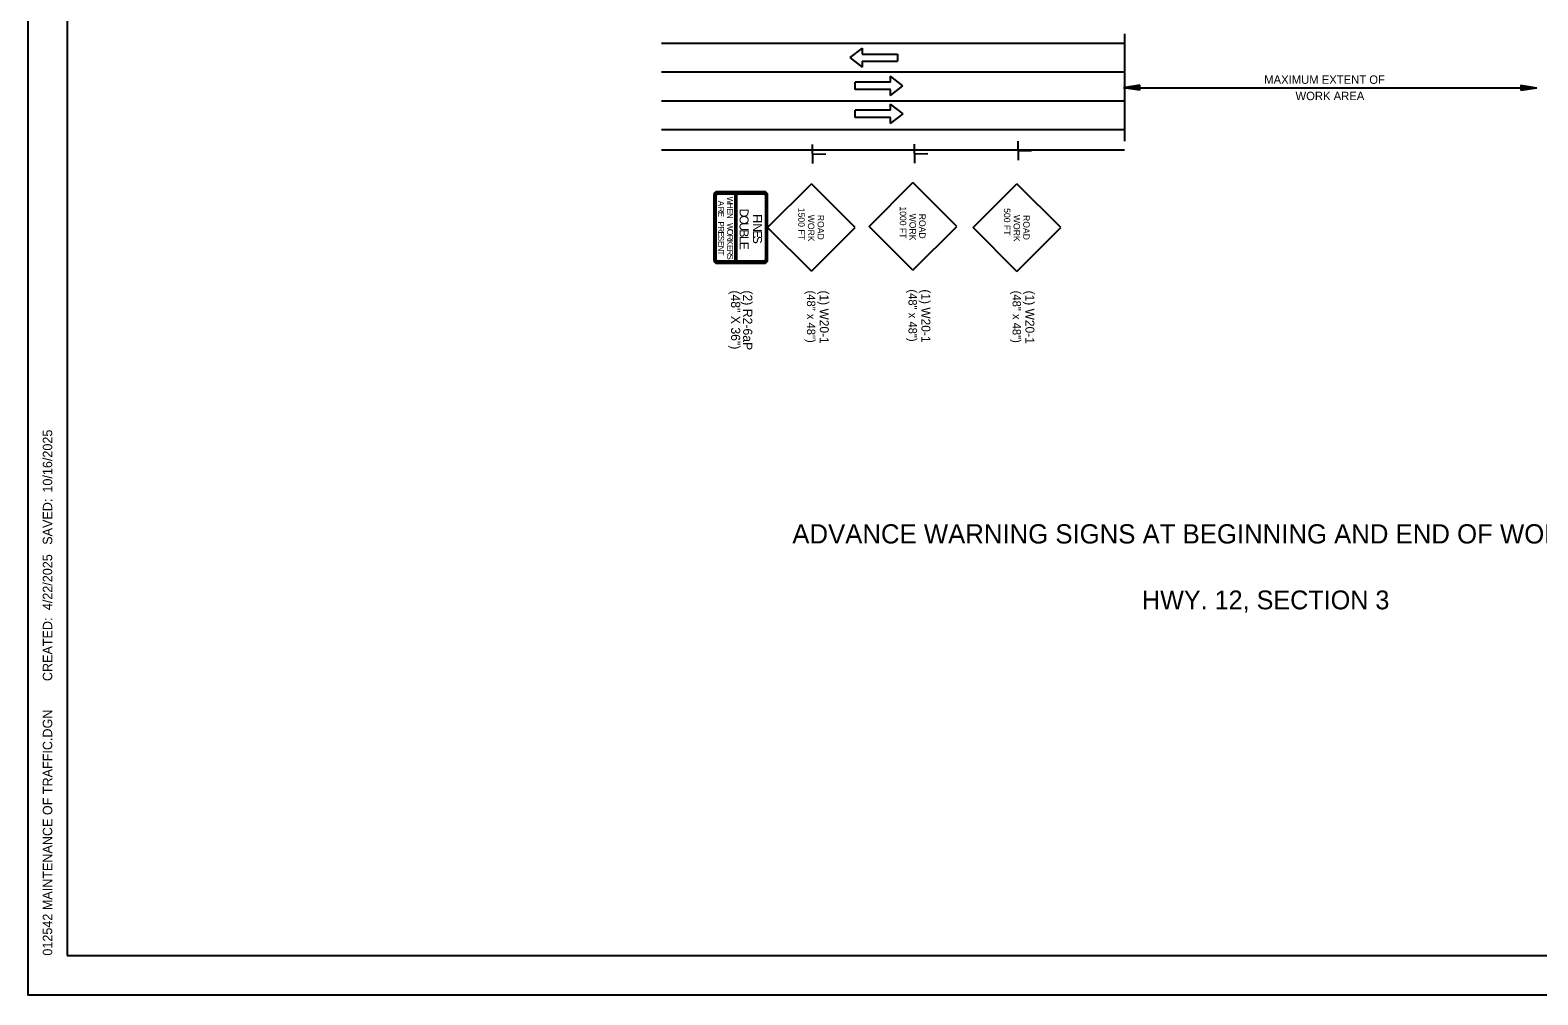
# Model space of a CAD drawing. Extents: x 32485 to 39285, y 55121 to 58033.
# Drawn here: x 35886 to 36848, y 56764 to 57379 of the extents above; entities that cross this region are included whole.
import ezdxf

# ---------------------------------------------------------------- set-up
doc = ezdxf.new("R2010")
doc.units = 0
for name, color, linetype in [('Default', 7, 'Continuous'), ('R_Border', 7, 'Continuous'), ('R_Border Notes', 7, 'Continuous'), ('R_Draft', 7, 'Continuous'), ('R_Exist Surface', 7, 'Continuous'), ('SHET_Annotations', 7, 'Continuous')]:
    doc.layers.add(name, color=color, linetype=linetype)

msp = doc.modelspace()

# ---------------------------------------------------------------- linework, layer by layer
at = {"layer": 'Default'}
for p, q in [((36584.44, 57376.82), (36584.44, 57308.4)), ((36417.17, 57367.79), (36409.21, 57361.65)), ((36417.17, 57367.79), (36417.17, 57363.95)), ((36409.21, 57361.65), (36417.17, 57355.51)), ((36417.17, 57363.95), (36439.74, 57363.95)), ((36417.17, 57359.35), (36439.74, 57359.35)), ((36417.17, 57359.35), (36417.17, 57355.51)), ((36439.74, 57363.95), (36439.74, 57359.35)), ((36435.16, 57345.92), (36435.16, 57349.76)), ((36443.13, 57343.62), (36435.16, 57349.76)), ((36435.16, 57345.92), (36412.59, 57345.92)), ((36412.59, 57341.32), (36412.59, 57345.92)), ((36435.16, 57341.32), (36412.59, 57341.32)), ((36435.16, 57337.48), (36443.13, 57343.62)), ((36435.16, 57337.48), (36435.16, 57341.32)), ((36583.93, 57342.47), (36847.55, 57342.47)), ((36641.23, 57342.47), (36790.25, 57342.47)), ((36435.27, 57328.12), (36412.7, 57328.12)), ((36412.7, 57323.52), (36412.7, 57328.12)), ((36435.27, 57328.12), (36435.27, 57331.96)), ((36443.24, 57325.82), (36435.27, 57331.96)), ((36435.27, 57323.52), (36412.7, 57323.52)), ((36435.27, 57319.68), (36443.24, 57325.82)), ((36435.27, 57319.68), (36435.27, 57323.52)), ((36322.59, 57274.02), (36322.59, 57232.62)), ((36323.18, 57274.02), (36323.18, 57232.62)), ((36324.02, 57232.62), (36324.02, 57274.02)), ((36354.71, 57276.16), (36324.73, 57276.16)), ((36354.71, 57275.56), (36324.73, 57275.56)), ((36324.73, 57274.73), (36354.71, 57274.73)), ((36336.21, 57231.9), (36336.21, 57274.73)), ((36336.21, 57274.73), (36337.04, 57274.73)), ((36337.04, 57274.73), (36337.04, 57231.9)), ((36355.43, 57274.02), (36355.43, 57232.62)), ((36356.26, 57232.62), (36356.26, 57274.02)), ((36356.85, 57232.62), (36356.85, 57274.02)), ((36354.71, 57231.9), (36324.73, 57231.9)), ((36337.04, 57231.9), (36336.21, 57231.9)), ((36324.73, 57231.07), (36354.71, 57231.07)), ((36324.73, 57230.47), (36354.71, 57230.47))]:
    msp.add_line(p, q, dxfattribs=at)
msp.add_lwpolyline([(35885, 57863.91), (35885, 56763.91), (37585, 56763.91), (37585, 57863.91)], close=True, dxfattribs=at)
for centre, radius, start, end in [((36324.73, 57274.02), 2.14, 90, 180.00001), ((36324.73, 57274.02), 1.55, 90.00001, 180), ((36324.73, 57274.02), 0.714, 90.00001, 180), ((36354.71, 57274.02), 2.14, 0, 90), ((36354.71, 57274.02), 1.55, 0, 90.00001), ((36354.71, 57274.02), 0.714, 0, 90.00001), ((36324.73, 57232.62), 2.14, 180.00001, 270.00001), ((36324.73, 57232.62), 1.55, 180, 270.00001), ((36324.73, 57232.62), 0.714, 180, 270.00001), ((36354.71, 57232.62), 2.14, 270, 0), ((36354.71, 57232.62), 1.55, 270, 0), ((36354.71, 57232.62), 0.714, 270, 0)]:
    msp.add_arc(centre, radius, start, end, dxfattribs=at)
at = {"layer": 'R_Border'}
for p, q in [((36385.59, 57294.1), (36385.38, 57306.15)), ((36385.66, 57300.1), (36393.89, 57300.24)), ((36450.68, 57294.4), (36450.48, 57306.45)), ((36450.75, 57300.4), (36458.98, 57300.54)), ((36516.84, 57296.31), (36516.64, 57308.36)), ((36516.92, 57302.31), (36525.14, 57302.45)), ((36356.85, 57253.32), (36384.73, 57281.22)), ((36412.63, 57253.32), (36384.73, 57281.22)), ((36421.65, 57254.03), (36449.53, 57281.93)), ((36477.43, 57254.03), (36449.53, 57281.93)), ((36488.02, 57253.22), (36515.9, 57281.13)), ((36543.8, 57253.22), (36515.9, 57281.13)), ((36384.73, 57225.42), (36356.85, 57253.32)), ((36384.73, 57225.42), (36412.63, 57253.32)), ((36449.53, 57226.13), (36421.65, 57254.03)), ((36449.53, 57226.13), (36477.43, 57254.03)), ((36515.9, 57225.32), (36488.02, 57253.22)), ((36515.9, 57225.32), (36543.8, 57253.22))]:
    msp.add_line(p, q, dxfattribs=at)
at = {"layer": 'R_Border Notes'}
for points in [[(35885, 56763.91), (37585, 56763.91), (37585, 57863.91), (35885, 57863.91)], [(35910, 56788.91), (37560, 56788.91), (37560, 57838.91), (35910, 57838.91)]]:
    msp.add_lwpolyline(points, close=True, dxfattribs=at)
at = {"layer": 'R_Draft'}
for p, q in [((36594.16, 57344.01), (36583.93, 57342.47)), ((36594.16, 57340.94), (36583.93, 57342.47)), ((36594.16, 57343.75), (36585.64, 57342.47)), ((36594.16, 57341.19), (36585.64, 57342.47)), ((36594.16, 57343.49), (36587.4, 57342.47)), ((36594.16, 57341.46), (36587.4, 57342.47)), ((36594.16, 57343.24), (36589.1, 57342.47)), ((36594.16, 57341.71), (36589.1, 57342.47)), ((36594.16, 57342.97), (36590.84, 57342.47)), ((36594.16, 57341.98), (36590.84, 57342.47)), ((36594.16, 57342.71), (36592.55, 57342.47)), ((36594.16, 57342.23), (36592.55, 57342.47)), ((36594.16, 57340.94), (36594.16, 57344.01)), ((36837.32, 57344.01), (36847.55, 57342.47)), ((36837.32, 57344.01), (36837.32, 57340.94)), ((36837.32, 57343.75), (36845.84, 57342.47)), ((36837.32, 57343.49), (36844.08, 57342.47)), ((36837.32, 57343.24), (36842.38, 57342.47)), ((36837.32, 57342.97), (36840.64, 57342.47)), ((36837.32, 57342.71), (36838.94, 57342.47)), ((36837.32, 57340.94), (36847.55, 57342.47)), ((36837.32, 57341.97), (36840.64, 57342.47)), ((36837.32, 57341.46), (36844.08, 57342.47)), ((36837.32, 57341.19), (36845.84, 57342.47)), ((36837.32, 57341.71), (36842.38, 57342.47)), ((36837.32, 57342.23), (36838.94, 57342.47))]:
    msp.add_line(p, q, dxfattribs=at)
at = {"layer": 'R_Exist Surface'}
for p, q in [((36289.08, 57370.98), (36584.44, 57370.98)), ((36289.08, 57352.58), (36584.44, 57352.58)), ((36289.08, 57334.17), (36584.44, 57334.17)), ((36289.08, 57315.76), (36584.44, 57315.76)), ((36289.05, 57302.95), (36584.42, 57302.95))]:
    msp.add_line(p, q, dxfattribs=at)

# ---------------------------------------------------------------- texts
at = {"layer": 'Default'}
for s, height, p in [('MAXIMUM EXTENT OF ', 5.3695, (36673.61, 57344.96)), ('WORK AREA', 5.37, (36693.57, 57334.54)), ('ADVANCE WARNING SIGNS AT BEGINNING AND END OF WORK ZONE ', 12.2732, (36372.6, 57051.78)), ('HWY. 12, SECTION 3', 12, (36595.63, 57009.79))]:
    msp.add_text(s, height=height, dxfattribs=at).set_placement(p)
for s, height, p in [('A', 3.81, (36325.27, 57270.37)), ('W', 3.81, (36330.98, 57273.02)), ('R', 3.81, (36325.27, 57266.56)), ('E', 3.81, (36325.27, 57263.33)), ('H', 3.81, (36330.98, 57269.06)), ('E', 3.81, (36330.98, 57265.56)), ('N', 3.81, (36330.98, 57262.55)), ('O', 5.71, (36338.95, 57261.08)), ('D', 5.71, (36338.95, 57265.31)), ('F', 5.71, (36347.51, 57261.83)), ('P', 3.81, (36325.27, 57257.16)), ('R', 3.81, (36325.27, 57254)), ('O', 3.81, (36330.98, 57252.27)), ('W', 3.81, (36330.98, 57256.15)), ('U', 5.71, (36338.95, 57256.57)), ('B', 5.71, (36338.95, 57252.12)), ('I', 5.71, (36347.51, 57258.11)), ('N', 5.71, (36347.51, 57256.06)), ('E', 5.71, (36347.51, 57251.6)), ('S', 3.81, (36325.27, 57248.02)), ('E', 3.81, (36325.27, 57250.77)), ('E', 3.81, (36325.27, 57244.79)), ('N', 3.81, (36325.27, 57241.78)), ('R', 3.81, (36330.98, 57248.73)), ('K', 3.81, (36330.98, 57245.49)), ('E', 3.81, (36330.98, 57242.18)), ('L', 5.71, (36338.95, 57247.95)), ('E', 5.71, (36338.95, 57244.24)), ('S', 5.71, (36347.51, 57248.01)), ('T', 3.81, (36325.27, 57238.62)), ('S', 3.81, (36330.98, 57236.2)), ('R', 3.81, (36330.98, 57239.17))]:
    msp.add_text(s, height=height, rotation=270, dxfattribs=at).set_placement(p)
at = {"layer": 'R_Border'}
for s, height, rotation, p in [('1500 FT', 4.11, 270.00057, (36376.37, 57265.89)), ('WORK', 4.11, 270.00004, (36382.54, 57261.46)), ('ROAD', 4.11, 270.00045, (36388.71, 57261.38)), ('1000 FT', 4.11, 270.00057, (36441.17, 57266.77)), ('WORK', 4.11, 270.00004, (36447.34, 57262.17)), ('ROAD', 4.11, 270.00045, (36453.5, 57262.09)), (' 500 FT', 4.11, 270.00057, (36507.55, 57267.17)), ('WORK', 4.11, 270.00004, (36513.71, 57261.36)), ('ROAD', 4.11, 270.00045, (36519.88, 57261.28)), ('(48" x 48")', 5.3523, 270, (36381.92, 57213.14)), ('(1) W20-1', 5.71, 270, (36390.13, 57213.14)), ('(48" x 48")', 5.3523, 270, (36446.71, 57213.86)), ('(1) W20-1', 5.71, 270, (36454.93, 57213.86)), ('(48" x 48")', 5.3523, 270, (36513.08, 57213.05)), ('(1) W20-1', 5.71, 270, (36521.3, 57213.05))]:
    msp.add_text(s, height=height, rotation=rotation, dxfattribs=at).set_placement(p)
at = {"layer": 'R_Draft'}
for s, height, p in [('(48" X 36")', 5.8301, (36333.51, 57213.19)), ('(2) R2-6aP', 5.83, (36341.24, 57213.19))]:
    msp.add_text(s, height=height, rotation=270, dxfattribs=at).set_placement(p)
at = {"layer": 'SHET_Annotations'}
for s, p in [('10/16/2025', (35900.5, 57084.25)), ('  SAVED: ', (35900.5, 57046.51)), ('4/22/2025', (35900.5, 57009.24)), ('     CREATED: ', (35900.5, 56952.88)), ('012542 MAINTENANCE OF TRAFFIC.DGN', (35900.5, 56788.91))]:
    msp.add_text(s, height=6, rotation=90, dxfattribs=at).set_placement(p)

doc.saveas('drawing.dxf')
